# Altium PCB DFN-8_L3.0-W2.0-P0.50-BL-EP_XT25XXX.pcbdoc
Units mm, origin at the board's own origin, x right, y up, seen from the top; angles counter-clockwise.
Board outline 15.2 x 16.45 mm, 2 copper layers (Top Layer, Bottom Layer), stack 0 mm thick; 1 components, 0 nets, 9 pads, 0 vias.
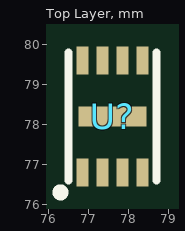
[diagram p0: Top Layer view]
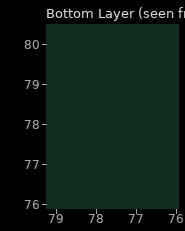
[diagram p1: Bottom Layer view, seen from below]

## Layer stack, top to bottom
Top Layer: signal copper (thickness not stored)
Bottom Layer: signal copper (thickness not stored)

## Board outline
85.05,69.85 69.85,69.85 69.85,86.3 85.05,86.3

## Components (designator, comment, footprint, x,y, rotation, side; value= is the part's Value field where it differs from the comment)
U? "" DFN-8_L3.0-W2.0-P0.50-BL-EP_XT25XXX 77.6,78.2 r0 top

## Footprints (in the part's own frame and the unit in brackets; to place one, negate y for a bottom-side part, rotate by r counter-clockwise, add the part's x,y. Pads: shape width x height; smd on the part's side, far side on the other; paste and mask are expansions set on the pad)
DFN-8_L3.0-W2.0-P0.50-BL-EP_XT25XXX [mm]
  rect 0.3x0.7 smd: 1(-0.75,-1.4) 2(-0.25,-1.4) 3(0.25,-1.4) 4(0.75,-1.4) 5(0.75,1.4) 6(0.25,1.4) 7(-0.25,1.4) 8(-0.75,1.4)
  rect 1.7x0.5 smd: 9(0,0)
  silkscreen extent -1.4,-2 1.1,1.6

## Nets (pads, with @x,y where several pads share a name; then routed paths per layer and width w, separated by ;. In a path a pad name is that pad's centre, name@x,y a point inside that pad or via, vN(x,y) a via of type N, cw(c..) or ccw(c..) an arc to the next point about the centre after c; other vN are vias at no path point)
pads on no net: U?.1 U?.2 U?.3 U?.4 U?.5 U?.6 U?.7 U?.8 U?.9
